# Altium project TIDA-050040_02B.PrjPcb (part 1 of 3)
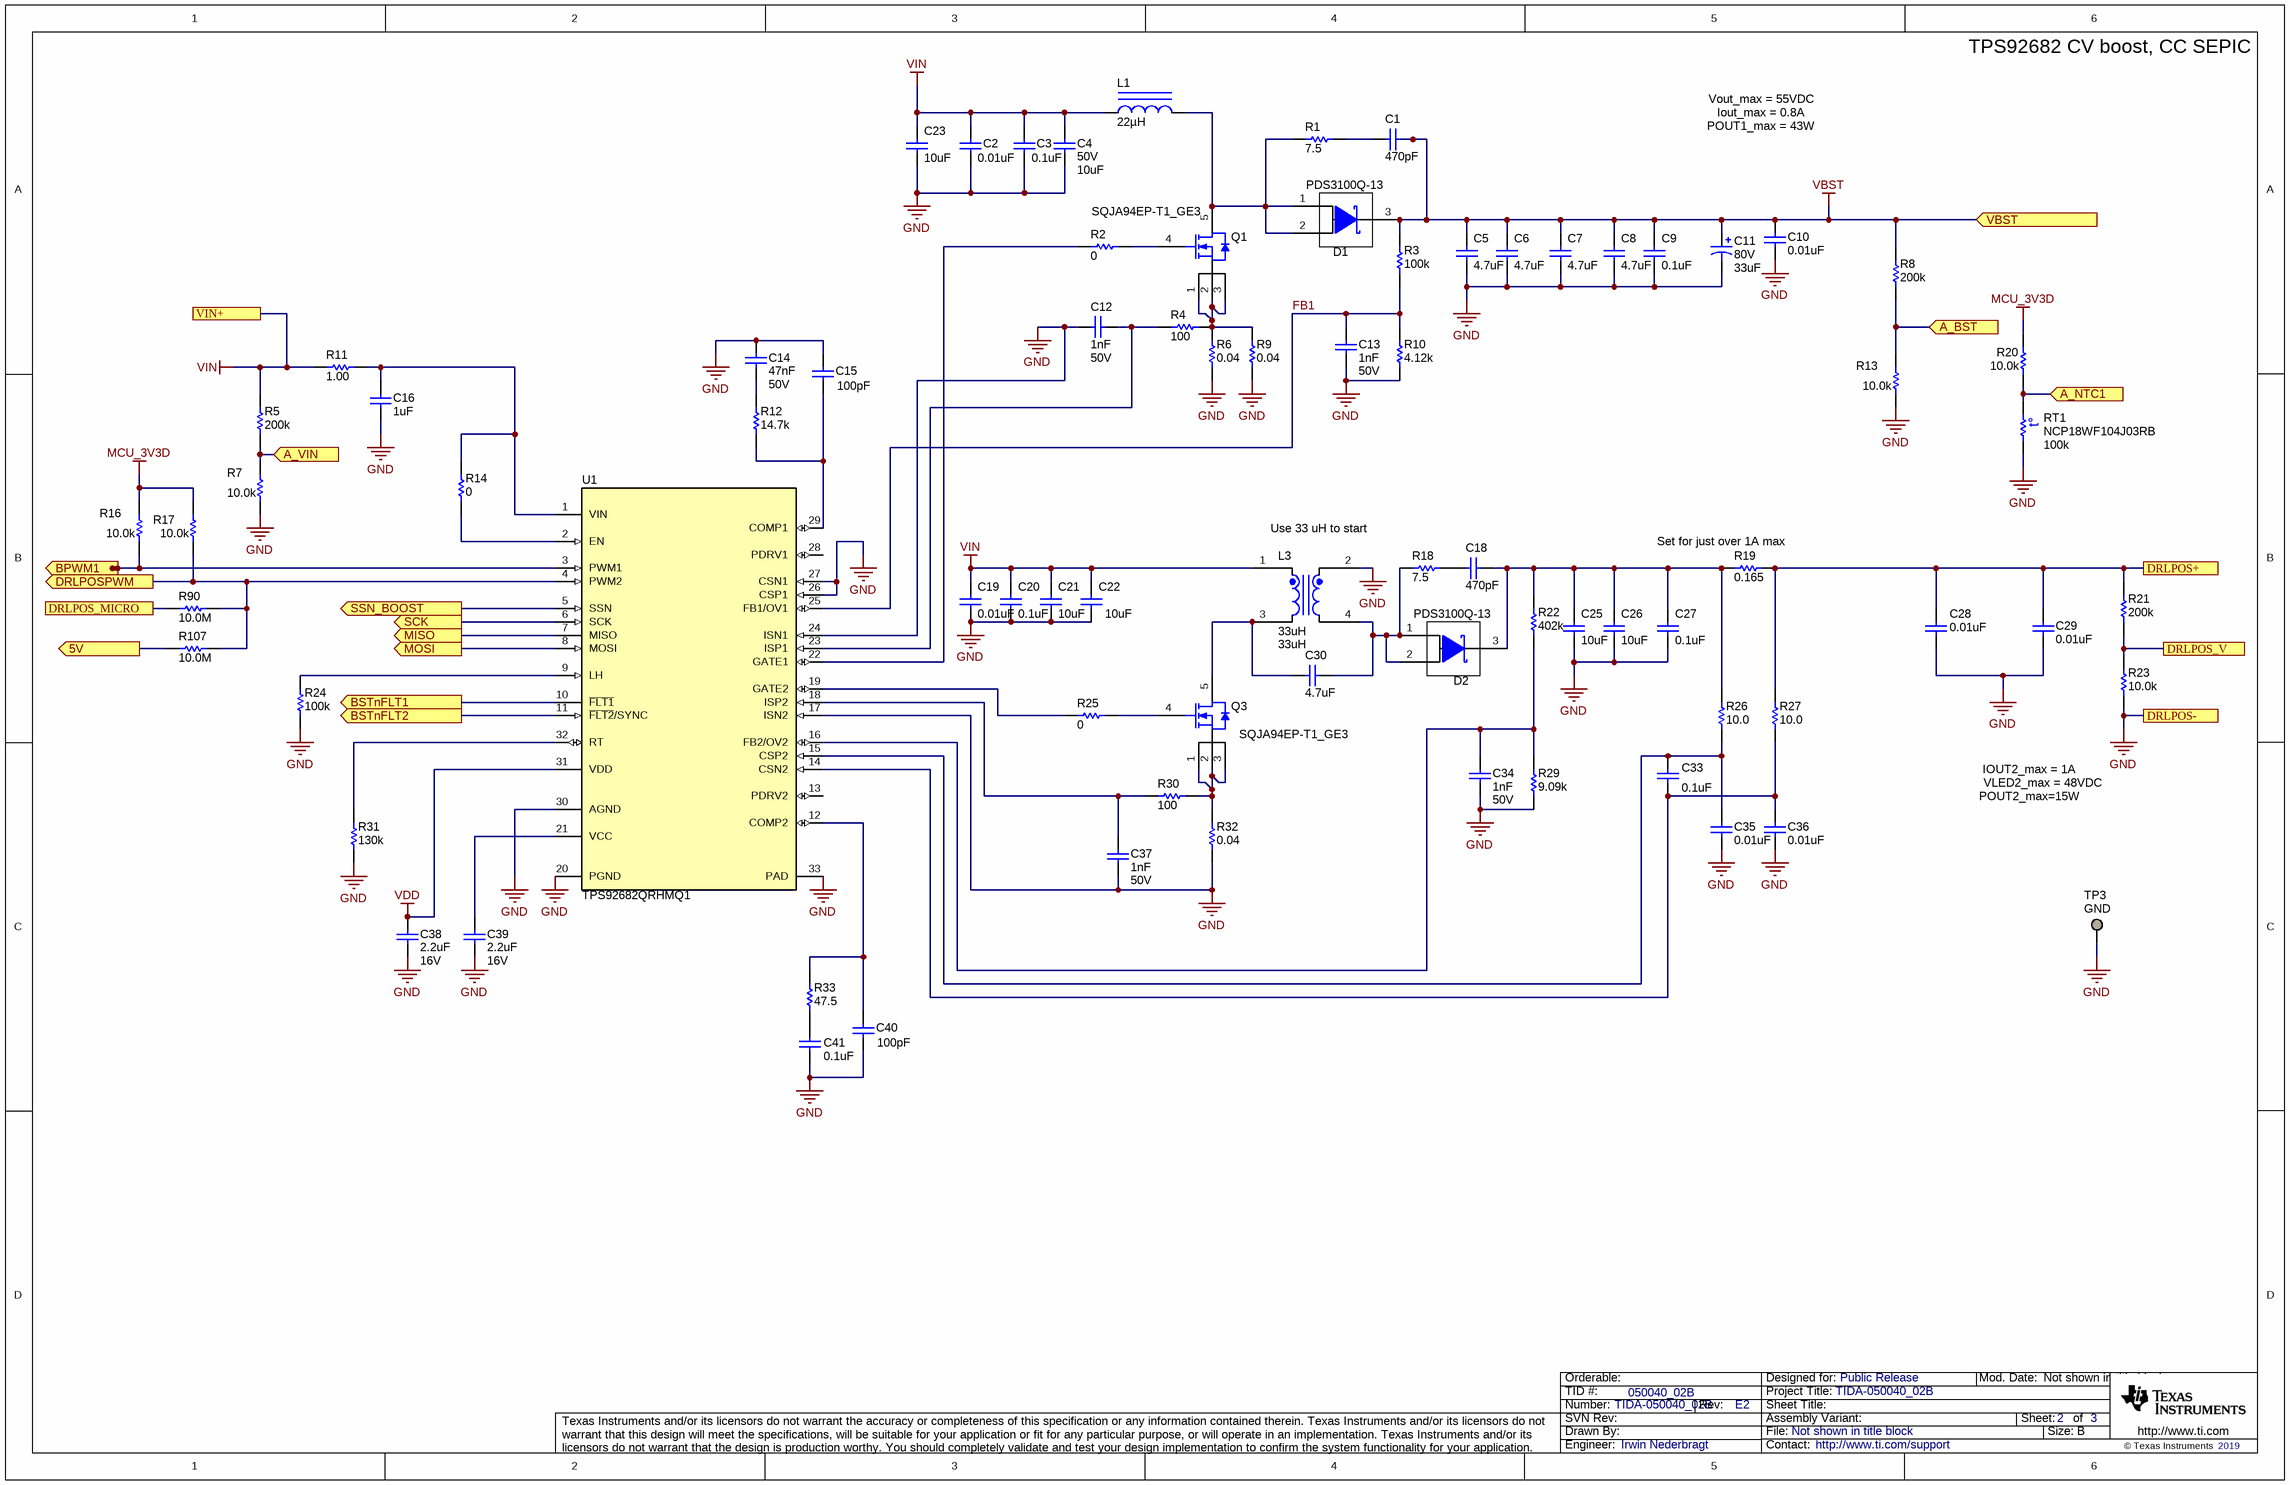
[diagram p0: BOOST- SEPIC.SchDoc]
CopyrightYear: 2019; PCB_Layout: Aaron Hanson; PCB_Rev: E2; PRJ_Customer: Public Release; PRJ_Engineer: Irwin Nederbragt; PRJ_Number: TIDA-050040_02B; PRJ_Title: TIDA-050040_02B; SCH_Rev: E2; TechSupport: http://www.ti.com/support; TID: 050040_02B
6 sheets, 346 parts. Net scope: flat (ports and power ports of the same name join across sheets).
Board file: TIDA-050040.PcbDoc
Sheets:
  BOOST- SEPIC.SchDoc
  Buck.SchDoc
  EVM_Hardware.SchDoc
  TIDA-050040_Battery.SchDoc
  TIDA-050040_MSP432E4x.SchDoc
  TIDA-050040_PwrSupplies.SchDoc

## Sheet BOOST- SEPIC.SchDoc
size 431 x 279 mm; Date: Not shown in title block; ApprovedBy: Not shown in title block; CheckedBy: Not shown in title block; Author: Not shown in title block; CompanyName: Not shown in title block; Engineer: Not shown in title block; Organization: Not shown in title block; Address1: Not shown in title block; Address2: Not shown in title block; Address3: Not shown in title block; Address4: Not shown in title block; DocumentNumber: 1; Revision: Use project parameter SCH_Rev; SheetNumber: 2; SheetTotal: 3; PageSetup: Record=PageOptions¦CenterHorizontal=True¦CenterVertical=True¦PrintScale=1.00¦XCorrection=1.00¦YCorrection=1.00¦PrintKind=0¦BorderSize=5000000¦LeftOffset=0¦BottomOffset=0¦Orientation=2¦PaperLength=1000¦PaperWidth=1000¦Scale=100¦PaperSource=15¦PrintQuality=600¦MediaType=1¦DitherType=10¦PaperKind=Letter¦PrintScaleMode=1

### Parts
C1  ValueDisplayed: 470pF  [0603_HV]  (hidden comment: Capacitor)
C2  ValueDisplayed: 0.01uF  [0603_HV]  (hidden comment: Capacitor)
C3  ValueDisplayed: 0.1uF  [0603_HV]  (hidden comment: Capacitor)
C4  VDC_V: 50V  ValueDisplayed: 10uF  [1210_280]  (hidden comment: C3225X7R1H106M250AC)
C5  ValueDisplayed: 4.7uF  [1210_220]  (hidden comment: Capacitor)
C6  ValueDisplayed: 4.7uF  [1210_220]  (hidden comment: Capacitor)
C7  ValueDisplayed: 4.7uF  [1210_220]  (hidden comment: Capacitor)
C8  ValueDisplayed: 4.7uF  [1210_220]  (hidden comment: Capacitor)
C9  ValueDisplayed: 0.1uF  [0603_HV]  (hidden comment: Capacitor)
C10  ValueDisplayed: 0.01uF  [0603_HV]  (hidden comment: Capacitor)
C11  VDC_V: 80V  ValueDisplayed: 33uF  [SM_RADIAL_F]  (hidden comment: EEE-FK1K330P)
C12  Cap_F: 1nF  VDC_V: 50V  [0603]  (hidden comment: C0603C102J5RACAUTO)
C13  Cap_F: 1nF  VDC_V: 50V  [0603]  (hidden comment: C0603C102J5RACAUTO)
C14  Cap_F: 47nF  VDC_V: 50V  [0603]  (hidden comment: 06035C473JAT2A)
C15  ValueDisplayed: 100pF  [0603_HV]  (hidden comment: 885012006057)
C16  ValueDisplayed: 1uF  [1206_180]  (hidden comment: Capacitor)
C18  ValueDisplayed: 470pF  [0603_HV]  (hidden comment: Capacitor)
C19  ValueDisplayed: 0.01uF  [0603_HV]  (hidden comment: Capacitor)
C20  ValueDisplayed: 0.1uF  [0603_HV]  (hidden comment: Capacitor)
C21  ValueDisplayed: 10uF  [1210_280]  (hidden comment: C3225X7R1H106M250AC)
C22  ValueDisplayed: 10uF  [1210_280]  (hidden comment: C3225X7R1H106M250AC)
C23  ValueDisplayed: 10uF  [1210_280]  (hidden comment: C3225X7R1H106M250AC)
C25  ValueDisplayed: 10uF  [1210_280]  (hidden comment: C3225X7R1H106M250AC)
C26  ValueDisplayed: 10uF  [1210_280]  (hidden comment: C3225X7R1H106M250AC)
C27  ValueDisplayed: 0.1uF  [0603_HV]  (hidden comment: Capacitor)
C28  ValueDisplayed: 0.01uF  [0603_HV]  (hidden comment: Capacitor)
C29  ValueDisplayed: 0.01uF  [0603_HV]  (hidden comment: Capacitor)
C30  ValueDisplayed: 4.7uF  [1210_220]  (hidden comment: Capacitor)
C33  ValueDisplayed: 0.1uF  [0603_HV]  (hidden comment: Capacitor)
C34  Cap_F: 1nF  VDC_V: 50V  [0603]  (hidden comment: C0603C102J5RACAUTO)
C35  ValueDisplayed: 0.01uF  [0603_HV]  (hidden comment: Capacitor)
C36  ValueDisplayed: 0.01uF  [0603_HV]  (hidden comment: Capacitor)
C37  Cap_F: 1nF  VDC_V: 50V  [0603]  (hidden comment: C0603C102J5RACAUTO)
C38  ValueDisplayed: 2.2uF  Value2: 16V  [0603_HV]  (hidden comment: Capacitor)
C39  ValueDisplayed: 2.2uF  Value2: 16V  [0603_HV]  (hidden comment: Capacitor)
C40  ValueDisplayed: 100pF  [0603_HV]  (hidden comment: 885012006057)
C41  ValueDisplayed: 0.1uF  [0603_HV]  (hidden comment: CGA3E3X7S2A104K080AB)
D1  PDS3100Q-13  [POWERDI5]
D2  PDS3100Q-13  [POWERDI5]
L1  ValueDisplayed: 22µH  [SPM12565VT]  (hidden comment: SPM12565VT-220M-D)
L3  value 33uH  [MSD1278]  (hidden comment: MSD1278-333ML)
Q1  SQJA94EP-T1_GE3  [PowerPAK_SO-8L]
Q3  SQJA94EP-T1_GE3  [PowerPAK_SO-8L]
R1  ValueDisplayed: 7.5  [2010L]  (hidden comment: Resistor)
R2  ValueDisplayed: 0  [0603_HV]  (hidden comment: CRCW06030000Z0EA)
R3  ValueDisplayed: 100k  [0603_HV]  (hidden comment: CRCW0603100KFKEA)
R4  ValueDisplayed: 100  [0603_HV]  (hidden comment: Resistor)
R5  ValueDisplayed: 200k  [0603]  (hidden comment: CRCW0603200KFKEA)
R6  ValueDisplayed: 0.04  [2010]  (hidden comment: CSRN2010FK40L0)
R7  ValueDisplayed: 10.0k  [0603]  (hidden comment: RMCF0603FT10K0)
R8  ValueDisplayed: 200k  [0603]  (hidden comment: CRCW0603200KFKEA)
R9  ValueDisplayed: 0.04  [2010]  (hidden comment: CSRN2010FK40L0)
R10  ValueDisplayed: 4.12k  [0603_HV]  (hidden comment: CRCW06034K12FKEA)
R11  ValueDisplayed: 1.00  [0805_HV]  (hidden comment: Resistor)
R12  ValueDisplayed: 14.7k  [0603_HV]  (hidden comment: ERJ-3EKF1472V)
R13  ValueDisplayed: 10.0k  [0603]  (hidden comment: RMCF0603FT10K0)
R14  ValueDisplayed: 0  [0603]  (hidden comment: CRCW06030000Z0EA)
R16  ValueDisplayed: 10.0k  [0603]  (hidden comment: RMCF0603FT10K0)
R17  ValueDisplayed: 10.0k  [0603]  (hidden comment: RMCF0603FT10K0)
R18  ValueDisplayed: 7.5  [2010L]  (hidden comment: Resistor)
R19  ValueDisplayed: 0.165  [1206]  (hidden comment: PT1206FR-070R165L)
R20  ValueDisplayed: 10.0k  [0603]  (hidden comment: RMCF0603FT10K0)
R21  ValueDisplayed: 200k  [0603]  (hidden comment: CRCW0603200KFKEA)
R22  ValueDisplayed: 402k  [0603_HV]  (hidden comment: CRCW0603402KFKEA)
R23  ValueDisplayed: 10.0k  [0603]  (hidden comment: CRCW060310K0FKEA)
R24  ValueDisplayed: 100k  [0603_HV]  (hidden comment: Resistor)
R25  ValueDisplayed: 0  [0603_HV]  (hidden comment: CRCW06030000Z0EA)
R26  ValueDisplayed: 10.0  [0603_HV]  (hidden comment: Resistor)
R27  ValueDisplayed: 10.0  [0603_HV]  (hidden comment: Resistor)
R29  ValueDisplayed: 9.09k  [0603_HV]  (hidden comment: CRCW06039K09FKEA)
R30  ValueDisplayed: 100  [0603_HV]  (hidden comment: Resistor)
R31  ValueDisplayed: 130k  [0603_HV]  (hidden comment: CRCW0603130KFKEA)
R32  ValueDisplayed: 0.04  [2010]  (hidden comment: CSRN2010FK40L0)
R33  ValueDisplayed: 47.5  [0603_HV]  (hidden comment: CRCW060347R5FKEA)
R90  ValueDisplayed: 10.0M  [0603]  (hidden comment: CRCW060310M0FKEA)
R107  ValueDisplayed: 10.0M  [0603]  (hidden comment: CRCW060310M0FKEA)
RT1  NCP18WF104J03RB  value 100k  [0603S]
TP3  GND  [Keystone1502-2]
U1  TPS92682QRHMQ1  [RHM0032C]

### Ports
5V, A_BST, A_NTC1, A_VIN, BPWM1, BSTnFLT1, BSTnFLT2, DRLPOS+, DRLPOS-, DRLPOS_MICRO, DRLPOS_V, DRLPOSPWM, MISO, MOSI, SCK, SSN_BOOST, VBST, VIN+

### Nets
5V: R107.1 ; port 5V
GND: C2.1 C3.1 C4.2 C5.2 C6.2 C7.2 C8.2 C9.2 C10.1 C11.2(-) C12.1 C13.1 C14.2 C15.1 C16.2 C19.1 C20.2 C21.2 C22.2 C23.2 C25.2 C26.2 C27.2 C28.2 C29.2 C34.1 C35.2 C36.2 C37.1 C38.1 C39.1 C40.2 C41.2 L3.2 R6.1 R7.1 R9.1 R10.1 R13.1 R23.1 R24.1 R29.1 R31.1 R32.1 RT1.1 TP3.1 U1.17(ISN2) U1.20(PGND) U1.24(ISN1) U1.26(CSP1) U1.27(CSN1) U1.30(AGND) U1.33(PAD) ; port DRLPOS-
MCU_3V3D: R16.2 R17.2 R20.2
VBST: C1.2 C5.1 C6.1 C7.1 C8.1 C9.1 C10.2 C11.1(+) D1.3(K) R3.2 R8.2 ; port VBST
VDD: C38.2 U1.31(VDD)
VIN: C2.2 C3.2 C4.1 C19.2 C20.1 C21.1 C22.1 C23.1 L1.1 L3.1 R5.2 R11.1 ; port VIN+
A_NTC1: R20.1 RT1.2 ; port A_NTC1
BPWM1: R16.1 U1.3(PWM1) ; port BPWM1
DRLPOS+: C28.1 C29.1 R19.2 R21.2 R27.2 ; port DRLPOS+
DRLPOS_MICRO: R90.1 ; port DRLPOS_MICRO
DRLPOSPWM: R17.1 R90.2 R107.2 U1.4(PWM2) ; port DRLPOSPWM
FB1: C13.2 R3.1 R10.2 U1.25(FB1/OV1)
MISOM: U1.7(MISO) ; port MISO
MOSIM: U1.8(MOSI) ; port MOSI
PD3: U1.6(SCK) ; port SCK
PE2: R21.1 R23.2 ; port DRLPOS_V
PE3: R5.1 R7.2 ; port A_VIN
PE4: R8.1 R13.2 ; port A_BST
PM1: U1.11(~{FLT2}/SYNC) ; port BSTnFLT2
PM2: U1.10(~{FLT1}) ; port BSTnFLT1
SSN_BOOST: U1.5(SSN) ; port SSN_BOOST
NetC1_1: C1.1 R1.1
NetC12_2: C12.2 R4.1 U1.23(ISP1)
NetC14_1: C14.1 R12.2
NetC15_2: C15.2 R12.1 U1.29(COMP1)
NetC16_1: C16.1 R11.2 R14.2 U1.1(VIN)
NetC18_1: C18.1 R18.1
NetC18_2: C18.2 C25.1 C26.1 C27.1 D2.3(K) R19.1 R22.2 R26.2
NetC30_1: C30.1 L3.3 Q3.5(D)
NetC30_2: C30.2 D2.1(A) D2.2(A) L3.4 R18.2
NetC33_1: C33.1 C35.1 R26.1 U1.15(CSP2)
NetC33_2: C33.2 C36.1 R27.1 U1.14(CSN2)
NetC34_2: C34.2 R22.1 R29.2 U1.16(FB2/OV2)
NetC37_2: C37.2 R30.1 U1.18(ISP2)
NetC39_2: C39.2 U1.21(VCC)
NetC40_1: C40.1 R33.2 U1.12(COMP2)
NetC41_1: C41.1 R33.1
NetD1_1: D1.1(A) D1.2(A) L1.2 Q1.5(D) R1.2
NetQ1_1: Q1.1(S) Q1.2(S) Q1.3(S) R4.2 R6.2 R9.2
NetQ1_4: Q1.4(G) R2.2
NetQ3_1: Q3.1(S) Q3.2(S) Q3.3(S) R30.2 R32.2
NetQ3_4: Q3.4(G) R25.2
NetR2_1: R2.1 U1.22(GATE1)
NetR14_1: R14.1 U1.2(EN)
NetR24_2: R24.2 U1.9(LH)
NetR25_1: R25.1 U1.19(GATE2)
NetR31_2: R31.2 U1.32(RT)

Not connected (* = marked no-connect by the designer): U1 13(PDRV2) 28(PDRV1)

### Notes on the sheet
- Vout_max = 55VDC
- TPS92682 CV boost, CC SEPIC
- Iout_max = 0.8A
- POUT1_max = 43W
- Use 33 uH to start
- (near R19) Set for just over 1A max
- IOUT2_max = 1A
- POUT2_max=15W
- VLED2_max = 48VDC

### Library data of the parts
C1 C18 = CMP-0007272-4: CAP, CERM, 470 pF, 100 V, +/- 5%, C0G/NP0, 0603; PartNumber: GRM1885C2A471JA01D; Manufacturer: MuRata; Polarized: N; Value: 470pF; U/M: EA; Value1: Unknown; VDC_V: 100V; TaMin_C: -55°C; TaMax_C: 125°C; Cap_Case: 0603; SizeArea_mm2: 1.28; SizeAreaWB_mm2: 4.68; SizeX_mm: 1.6; SizeY_mm: 0.8; SizeZ_mm: 1; AEC Category: Q200
C2 C10 C19 C28 C29 C35 C36 = CMP-0007082-4: CAP, CERM, 0.01 uF, 100 V, +/- 10%, X7R, AEC-Q200 Grade 1, 0603; PartNumber: CGA3E2X7R2A103K080AA; Manufacturer: TDK; Polarized: N; Value: 0.01uF; U/M: EA; Cap_F: 10nF; ESR_ohm: 2.35428d; Value1: 0.235428 ohm; VDC_V: 100V; IRMS_A: 3.96995dA; TaMin_C: -55°C; TaMax_C: 125°C; Cap_Case: 0603; SizeArea_mm2: 1.28; SizeAreaWB_mm2: 4.68; SizeX_mm: 1.6; SizeY_mm: 0.8; SizeZ_mm: 1; AEC Category: Q200; AEC Qualified: Y
C3 C9 C20 C27 C33 = CMP-0007469-4: CAP, CERM, 0.1 uF, 100 V, +/- 10%, X7R, 0603; PartNumber: GRM188R72A104KA35D; Manufacturer: MuRata; Polarized: N; Value: 0.1uF; U/M: EA; Cap_F: 100nF; Value1: Unknown; VDC_V: 100V; TaMin_C: -55°C; TaMax_C: 125°C; Cap_Case: 0603; SizeArea_mm2: 1.28; SizeAreaWB_mm2: 4.68; SizeX_mm: 1.6; SizeY_mm: 0.8; SizeZ_mm: 1; AEC Category: Q200
C4 = CMP-0009120-1: CAP, CERM, 10 uF, 50 V, +/- 20%, X7R, 1210; Manufacturer: TDK; TaMin_C: -55°C; Polarized: N; SizeAreaWB_mm2: 14.7; Value1: Unknown; U/M: EA; Value: 10uF; TaMax_C: 125°C; SizeZ_mm: 2.8; SizeX_mm: 3.2; SizeY_mm: 2.5; Cap_Case: 1210; SizeArea_mm2: 8; CompType: Capacitor; Cap_F: 10µF; AEC Category: Q200
C5-C8 C30 = CMP-0009134-2: CAP, CERM, 4.7 uF, 100 V, +/- 10%, X7S, 1210; PartNumber: C3225X7S2A475K200AB; Manufacturer: TDK; Polarized: N; Value: 4.7uF; U/M: EA; Cap_F: 4.7µF; ESR_ohm: 4.236m; Value1: 0.004236 ohm; VDC_V: 100V; IRMS_A: 3.57337A; TaMin_C: -55°C; TaMax_C: 125°C; SizeArea_mm2: 8; SizeAreaWB_mm2: 14.7; SizeX_mm: 3.2; SizeY_mm: 2.5; SizeZ_mm: 2.2; AEC Category: Q200
C11 = CMP-0011198-2: CAP, AL, 33 uF, 80 V, +/- 20%, 1.3 ohm, AEC-Q200 Grade 2, SMD; Manufacturer: Panasonic; TaMin_C: -55°C; ESR_ohm: 1.3; Polarized: Y; SizeAreaWB_mm2: 123.6; Value1: 1.3 ohm; U/M: EA; Value: 33uF; TaMax_C: 105°C; SizeZ_mm: 10.2; SizeX_mm: 10; SizeY_mm: 8.3; Cap_Case: F; SizeArea_mm2: 83; CompType: Capacitor; Cap_F: 33µF; IRMS_A: 1.3dA; AEC Grade: 2; AEC Category: Q200
C12 C13 C34 C37 = CMP-0006844-4: CAP, CERM, 1000 pF, 50 V, +/- 5%, X7R, AEC-Q200 Grade 1, 0603; Manufacturer: Kemet; TaMin_C: -55°C; Polarized: N; SizeAreaWB_mm2: 4.68; Value1: Unknown; U/M: EA; Value: 1000pF; TaMax_C: 125°C; SizeZ_mm: 1; SizeX_mm: 1.6; SizeY_mm: 0.8; SizeArea_mm2: 1.28; CompType: Capacitor; AEC Qualified: Y; AEC Category: Q200
C14 = CMP-0085252-1: CAP, CERM, 0.047 µF, 50 V,+/- 5%, X7R, 0603; Manufacturer: AVX; TaMax_C: 125°C; Value: 0.047uF; SizeX_mm: 1.6; SizeArea_mm2: 1.28; AEC Category: Q200; SizeY_mm: 0.8; Polarized: N; CompType: Capacitor; SizeAreaWB_mm2: 4.68; U/M: EA; TaMin_C: -55°C; SizeZ_mm: 1
C15 C40 = CMP-0006822-4: CAP, CERM, 100 pF, 50 V, +/- 5%, C0G/NP0, 0603; Manufacturer: Wurth Elektronik; TaMin_C: -55°C; Polarized: N; SizeAreaWB_mm2: 4.68; Value1: Unknown; U/M: EA; Value: 100pF; TaMax_C: 125°C; SizeZ_mm: 1; SizeX_mm: 1.6; SizeY_mm: 0.8; Cap_Case: 0603; Value2: 50V; SizeArea_mm2: 1.28; CompType: Capacitor; AEC Category: Q200
C16 = CMP-0008801-2: CAP, CERM, 1 uF, 100 V, +/- 10%, X7R, 1206; PartNumber: CL31B105KCHNNNE; Manufacturer: Samsung; Polarized: N; Value: 1uF; U/M: EA; Cap_F: 1µF; Value1: Unknown; VDC_V: 100V; TaMin_C: -55°C; TaMax_C: 125°C; Cap_Case: 1206; SizeArea_mm2: 5.12; SizeAreaWB_mm2: 10.92; SizeX_mm: 3.2; SizeY_mm: 1.6; SizeZ_mm: 1.8; AEC Category: Q200
C21-C23 C25 C26 = CMP-0009120-1: CAP, CERM, 10 uF, 50 V, +/- 20%, X7R, 1210; Manufacturer: TDK; TaMin_C: -55°C; Polarized: N; SizeAreaWB_mm2: 14.7; Value1: Unknown; U/M: EA; Value: 10uF; TaMax_C: 125°C; SizeZ_mm: 2.8; SizeX_mm: 3.2; SizeY_mm: 2.5; Cap_Case: 1210; Value2: 50V; SizeArea_mm2: 8; CompType: Capacitor; Cap_F: 10µF; AEC Category: Q200
C38 C39 = CMP-0007499-4: CAP, CERM, 2.2 uF, 16 V, +/- 10%, X7R, 0603; PartNumber: GRM188Z71C225KE43; Manufacturer: MuRata; Polarized: N; Value: 2.2uF; U/M: EA; Cap_F: 2.2µF; Value1: Unknown; TaMin_C: -55°C; TaMax_C: 125°C; Cap_Case: 0603; SizeArea_mm2: 1.28; SizeAreaWB_mm2: 4.68; SizeX_mm: 1.6; SizeY_mm: 0.8; SizeZ_mm: 1; AEC Category: Q200
C41 = CMP-0007099-4: CAP, CERM, 0.1 uF, 100 V, +/- 10%, X7S, AEC-Q200 Grade 1, 0603; Manufacturer: TDK; TaMin_C: -55°C; ESR_ohm: 0.04959; Polarized: N; SizeAreaWB_mm2: 4.68; Value1: 0.04959 ohm; U/M: EA; Value: 0.1uF; TaMax_C: 125°C; SizeZ_mm: 1; SizeX_mm: 1.6; SizeY_mm: 0.8; Cap_Case: 0603; SizeArea_mm2: 1.28; CompType: Capacitor; AEC Qualified: Y; Cap_F: 100nF; VDC_V: 100V; IRMS_A: 7.51618dA; AEC Category: Q200
D1 D2 = CMP-0028754-2: Diode, Schottky, 100 V, 3 A, AEC-Q101, PowerDI5; Manufacturer: Diodes Inc.; Vf_V: 7.6dV; Value: 100V; Value1: 3A; Value2: 0.76V; TJmax_C: 150°C; SizeAreaWB_mm2: 49.56; SizeArea_mm2: 24.96; SizeX_mm: 6.4; SizeY_mm: 3.9; SizeZ_mm: 1.05; AEC Category: Q101; AEC Qualified: Y; Green_Lifecycle: Active; Green_REACh: Passed
L1 = CMP-0084138-1: Inductor, Shielded, 22 µH, 6.9 A, 0.0341 ohm, AEC-Q200 Grade 0, SMD; Manufacturer: TDK; Isat: 14.1A @ 30% inductance drop; Irms: 6.9A @ 40C rise; SizeAreaWB_mm2: 217.5; DCR_ohm: 0.0341; Value: 22uH; Imax_A: 6.9A; SizeZ_mm: 6.5; SizeX_mm: 13; SizeY_mm: 12.5; SizeArea_mm2: 162.5; AEC Qualified: Y; AEC Grade: 0; AEC Category: Q200
L3 = CMP-0012870-2: Coupled inductor, 33 uH, 5.6 A, 0.15 ohm, TH; Manufacturer: Coilcraft; SizeAreaWB_mm2: 204.49; DCR_ohm: 1.5d; SizeZ_mm: 8.05; SizeX_mm: 12.3; SizeArea_mm2: 151.29; Ind_H: 33µH
Q1 Q3 = CMP-0086155-1: MOSFET, N-CH, 80 V, 60 A, AEC-Q101, PowerPAK_SO-8L; Alternate Manufacturer: None; Manufacturer: Vishay-Siliconix; IdsMax_A: 60A; SizeZ_mm: 1.14; SizeArea_mm2: 31.5495; ChMode: Enhancement; AEC Category: Q101; AEC Qualified: Y; Vgs_V: 20V; SizeAreaWB_mm2: 58.1095; Value2: 36 nC; Value1: ? ohm; VdsMax_V: 80V; Value: 80V; QgTyp_nC: 36; SizeY_mm: 5.13; SizeX_mm: 6.15; ChType: N
R1 R18 = CMP-0016180-3: RES, 7.5, 5%, 0.75 W, AEC-Q200 Grade 0, 2010; PartNumber: CRCW20107R50JNEF; Manufacturer: Vishay-Dale; Value: 7.5; Value_Code: 7R50; Power_W: 750mW; Value2: 0.75W; VDC_V: 400V; TempCo: 200 ppm/C; EIA_Code: E24; AEC Category: Q200; AEC Qualified: Y; AEC Grade: 0; SizeArea_mm2: 12.5; SizeX_mm: 5; SizeY_mm: 2.5; SizeZ_mm: 1.66
R2 R25 = CMP-0025697-4: RES, 0, 5%, 0.1 W, AEC-Q200 Grade 0, 0603; Manufacturer: Vishay-Dale; Power_W: 100mW; TempCo: 200 ppm/C; Value_Code: 0000; Value: 0; EIA_Code: E24; SizeX_mm: 1.6; SizeY_mm: 0.8; SizeZ_mm: 1; Value2: 0.1W; SizeArea_mm2: 1.28; CompType: Resistor; AEC Qualified: Y; VDC_V: 75V; AEC Category: Q200
R3 = CMP-0021990-4: RES, 100 k, 1%, 0.1 W, AEC-Q200 Grade 0, 0603; Manufacturer: Vishay-Dale; Power_W: 100mW; TempCo: 100 ppm/C; Value: 100k; EIA_Code: E96; SizeX_mm: 1.6; SizeY_mm: 0.8; SizeZ_mm: 1; Value2: 0.1W; SizeArea_mm2: 1.28; CompType: Resistor; AEC Qualified: Y; VDC_V: 75V; AEC Category: Q200; AEC Grade: 0
R4 R30 = CMP-0021991-4: RES, 100, 1%, 0.1 W, AEC-Q200 Grade 0, 0603; PartNumber: CRCW0603100RFKEA; Manufacturer: Vishay-Dale; Value: 100; Value_Code: 100R; Power_W: 100mW; Value2: 0.1W; VDC_V: 75V; TempCo: 100 ppm/C; SizeArea_mm2: 1.28; SizeX_mm: 1.6; SizeY_mm: 0.8; SizeZ_mm: 1; EIA_Code: E96; AEC Category: Q200; AEC Qualified: Y; AEC Grade: 0
R5 R8 R21 = CMP-0022200-4: RES, 200 k, 1%, 0.1 W, AEC-Q200 Grade 0, 0603; Manufacturer: Vishay-Dale; Power_W: 100mW; TempCo: 100 ppm/C; Value: 200k; EIA_Code: E96; SizeX_mm: 1.6; SizeY_mm: 0.8; SizeZ_mm: 1; Value2: 0.1W; SizeArea_mm2: 1.28; CompType: Resistor; AEC Qualified: Y; VDC_V: 75V; AEC Category: Q200; AEC Grade: 0
R6 R9 R32 = CMP-0016519-2: RES, 0.04, 1%, 1 W, 2010; Manufacturer: Stackpole Electronics Inc; Power_W: 1W; TempCo: 250 ppm/C; Value_Code: R040; U/M: EA; Value: 0.04; SizeX_mm: 5; SizeY_mm: 2.5; SizeZ_mm: 1.66; SizeArea_mm2: 12.5; AEC Category: Q200
R7 R13 R16 R17 R20 = CMP-0023341-3: RES, 10.0 k, 1%, 0.1 W, AEC-Q200 Grade 0, 0603; Manufacturer: Stackpole Electronics Inc; Power_W: 100mW; TempCo: 100 ppm/C; Value_Code: 10k0; U/M: EA; Value: 10.0k; EIA_Code: E96; Res_ohm: 10k; SizeX_mm: 1.6; SizeY_mm: 0.8; SizeZ_mm: 1; Value2: 0.1W; SizeArea_mm2: 1.28; CompType: Resistor; AEC Qualified: Y; VDC_V: 75V; AEC Grade: 0; AEC Category: Q200
R10 = CMP-0022450-4: RES, 4.12 k, 1%, 0.1 W, AEC-Q200 Grade 0, 0603; Manufacturer: Vishay-Dale; Power_W: 100mW; TempCo: 100 ppm/C; Value_Code: 4k12; Value: 4.12k; EIA_Code: E96; SizeX_mm: 1.6; SizeY_mm: 0.8; SizeZ_mm: 1; Value2: 0.1W; SizeArea_mm2: 1.28; CompType: Resistor; AEC Qualified: Y; VDC_V: 75V; AEC Category: Q200; AEC Grade: 0
R11 = CMP-0021009-3: RES, 1.00, 1%, 0.125 W, AEC-Q200 Grade 0, 0805; PartNumber: CRCW08051R00FKEA; Manufacturer: Vishay-Dale; Value: 1.00; Res_ohm: 1; Value_Code: 1R00; Power_W: 125mW; Value2: 0.125W; VDC_V: 150V; TempCo: 100 ppm/C; SizeArea_mm2: 2.5; SizeX_mm: 2; SizeY_mm: 1.25; SizeZ_mm: 1.45; EIA_Code: E96; AEC Category: Q200; AEC Qualified: Y; AEC Grade: 0
R12 = CMP-0022687-3: RES, 14.7 k, 1%, 0.1 W, AEC-Q200 Grade 0, 0603; Manufacturer: Panasonic; Power_W: 100mW; TempCo: 100 ppm/C; Value_Code: 14k7; U/M: EA; Value: 14.7k; EIA_Code: E96; SizeX_mm: 1.6; SizeY_mm: 0.8; SizeZ_mm: 1; Value2: 0.1W; SizeArea_mm2: 1.28; CompType: Resistor; AEC Qualified: Y; VDC_V: 50V; AEC Grade: 0; AEC Category: Q200
R14 = CMP-0025697-4: RES, 0, 5%, 0.1 W, AEC-Q200 Grade 0, 0603; Manufacturer: Vishay-Dale; Power_W: 100mW; TempCo: 200 ppm/C; Value_Code: 0000; Value: 0; EIA_Code: E24; SizeX_mm: 1.6; SizeY_mm: 0.8; SizeZ_mm: 1; Value2: 0.1W; SizeArea_mm2: 1.28; AEC Qualified: Y; VDC_V: 75V; AEC Category: Q200
R19 = CMP-0017835-2: RES, 0.165, 1%, 0.25 W, 1206; Manufacturer: Yageo America; Power_W: 250mW; TempCo: 75 ppm/C; Value_Code: R165; U/M: EA; Value: 0.165; Res_ohm: 1.65d; SizeX_mm: 3.2; SizeY_mm: 1.6; SizeZ_mm: 1.35; Value2: 0.25W; SizeArea_mm2: 5.12; AEC Qualified: N; AEC Category: Q200
R22 = CMP-0022408-4: RES, 402 k, 1%, 0.1 W, AEC-Q200 Grade 0, 0603; Manufacturer: Vishay-Dale; Power_W: 100mW; TempCo: 100 ppm/C; Value: 402k; EIA_Code: E96; SizeX_mm: 1.6; SizeY_mm: 0.8; SizeZ_mm: 1; Value2: 0.1W; SizeArea_mm2: 1.28; CompType: Resistor; AEC Qualified: Y; VDC_V: 75V; AEC Category: Q200; AEC Grade: 0
R23 = CMP-0021998-4: RES, 10.0 k, 1%, 0.1 W, AEC-Q200 Grade 0, 0603; Manufacturer: Vishay-Dale; Power_W: 100mW; TempCo: 100 ppm/C; Value_Code: 10k0; Value: 10.0k; EIA_Code: E96; Res_ohm: 10k; SizeX_mm: 1.6; SizeY_mm: 0.8; SizeZ_mm: 1; Value2: 0.1W; SizeArea_mm2: 1.28; CompType: Resistor; AEC Qualified: Y; VDC_V: 75V; AEC Category: Q200; AEC Grade: 0
R24 = CMP-0021990-4: RES, 100 k, 1%, 0.1 W, AEC-Q200 Grade 0, 0603; PartNumber: CRCW0603100KFKEA; Manufacturer: Vishay-Dale; Value: 100k; Power_W: 100mW; Value2: 0.1W; VDC_V: 75V; TempCo: 100 ppm/C; SizeArea_mm2: 1.28; SizeX_mm: 1.6; SizeY_mm: 0.8; SizeZ_mm: 1; EIA_Code: E96; AEC Category: Q200; AEC Qualified: Y; AEC Grade: 0
R26 R27 = CMP-0022003-4: RES, 10.0, 1%, 0.1 W, AEC-Q200 Grade 0, 0603; PartNumber: CRCW060310R0FKEA; Manufacturer: Vishay-Dale; Value: 10.0; Res_ohm: 10; Value_Code: 10R0; Power_W: 100mW; Value2: 0.1W; VDC_V: 75V; TempCo: 100 ppm/C; SizeArea_mm2: 1.28; SizeX_mm: 1.6; SizeY_mm: 0.8; SizeZ_mm: 1; EIA_Code: E96; AEC Category: Q200; AEC Qualified: Y; AEC Grade: 0
R29 = CMP-0022665-4: RES, 9.09 k, 1%, 0.1 W, AEC-Q200 Grade 0, 0603; Manufacturer: Vishay-Dale; Power_W: 100mW; TempCo: 100 ppm/C; Value_Code: 9k09; Value: 9.09k; EIA_Code: E96; SizeX_mm: 1.6; SizeY_mm: 0.8; SizeZ_mm: 1; Value2: 0.1W; SizeArea_mm2: 1.28; CompType: Resistor; AEC Qualified: Y; VDC_V: 75V; AEC Category: Q200; AEC Grade: 0
R31 = CMP-0022036-4: RES, 130 k, 1%, 0.1 W, AEC-Q200 Grade 0, 0603; Manufacturer: Vishay-Dale; Power_W: 100mW; TempCo: 100 ppm/C; Value: 130k; EIA_Code: E96; SizeX_mm: 1.6; SizeY_mm: 0.8; SizeZ_mm: 1; Value2: 0.1W; SizeArea_mm2: 1.28; CompType: Resistor; AEC Qualified: Y; VDC_V: 75V; AEC Category: Q200; AEC Grade: 0
R33 = CMP-0022440-4: RES, 47.5, 1%, 0.1 W, AEC-Q200 Grade 0, 0603; Manufacturer: Vishay-Dale; Power_W: 100mW; TempCo: 100 ppm/C; Value_Code: 47R5; Value: 47.5; EIA_Code: E96; SizeX_mm: 1.6; SizeY_mm: 0.8; SizeZ_mm: 1; Value2: 0.1W; SizeArea_mm2: 1.28; CompType: Resistor; AEC Qualified: Y; VDC_V: 75V; AEC Category: Q200; AEC Grade: 0
R90 R107 = CMP-0022002-4: RES, 10.0 M, 1%, 0.1 W, AEC-Q200 Grade 0, 0603; Manufacturer: Vishay-Dale; Power_W: 100mW; TempCo: 100 ppm/C; Value_Code: 10M0; Value: 10.0Meg; EIA_Code: E96; Res_ohm: 10M; SizeX_mm: 1.6; SizeY_mm: 0.8; SizeZ_mm: 1; Value2: 0.1W; SizeArea_mm2: 1.28; AEC Qualified: Y; VDC_V: 75V; AEC Category: Q200; AEC Grade: 0
RT1 = CMP-0002534-3: Thermistor NTC, 100k ohm, 5%, 0603; Manufacturer: MuRata; TaMax_C: 125°C; SizeX_mm: 1.6; SizeY_mm: 0.8; TaMin_C: -40°C; Power_W: 100mW; SizeZ_mm: 1; SizeArea_mm2: 1.28; SizeAreaWB_mm2: 4.68; U/M: EA
TP3 = CMP-0055113-1: Terminal, Turret, TH, Double; PartNumber: 1502-2; Manufacturer: Keystone; CompType: Turret Terminal; Green_Lifecycle: Active; Green_REACh: Passed; CNHeader: FALSE
U1 = CMP-0084188-3: Dual Channel Constant Voltage and Constant Current Controller with SPI Interface, RHM0032C (VQFNP-32); Alternate Manufacturer: Texas Instruments; SizeAreaWB_mm2: 49; Rating: Automotive; SizeZ_mm: 0.9; SizeX_mm: 5; SizeArea_mm2: 25; CompType: IC; AEC Qualified: Y; AEC Category: Q200

## Sheet Buck.SchDoc
size 431 x 279 mm; Date: Not shown in title block; ApprovedBy: Not shown in title block; CheckedBy: Not shown in title block; Author: Not shown in title block; CompanyName: Not shown in title block; Engineer: Not shown in title block; Organization: Not shown in title block; Address1: Not shown in title block; Address2: Not shown in title block; Address3: Not shown in title block; Address4: Not shown in title block; DocumentNumber: 1; Revision: Use project parameter SCH_Rev; SheetNumber: 2; SheetTotal: 3; PageSetup: Record=PageOptions¦CenterHorizontal=True¦CenterVertical=True¦PrintScale=1.00¦XCorrection=1.00¦YCorrection=1.00¦PrintKind=0¦BorderSize=5000000¦LeftOffset=0¦BottomOffset=0¦Orientation=2¦PaperLength=1000¦PaperWidth=1000¦Scale=100¦PaperSource=15¦PrintQuality=600¦MediaType=1¦DitherType=10¦PaperKind=Letter¦PrintScaleMode=1
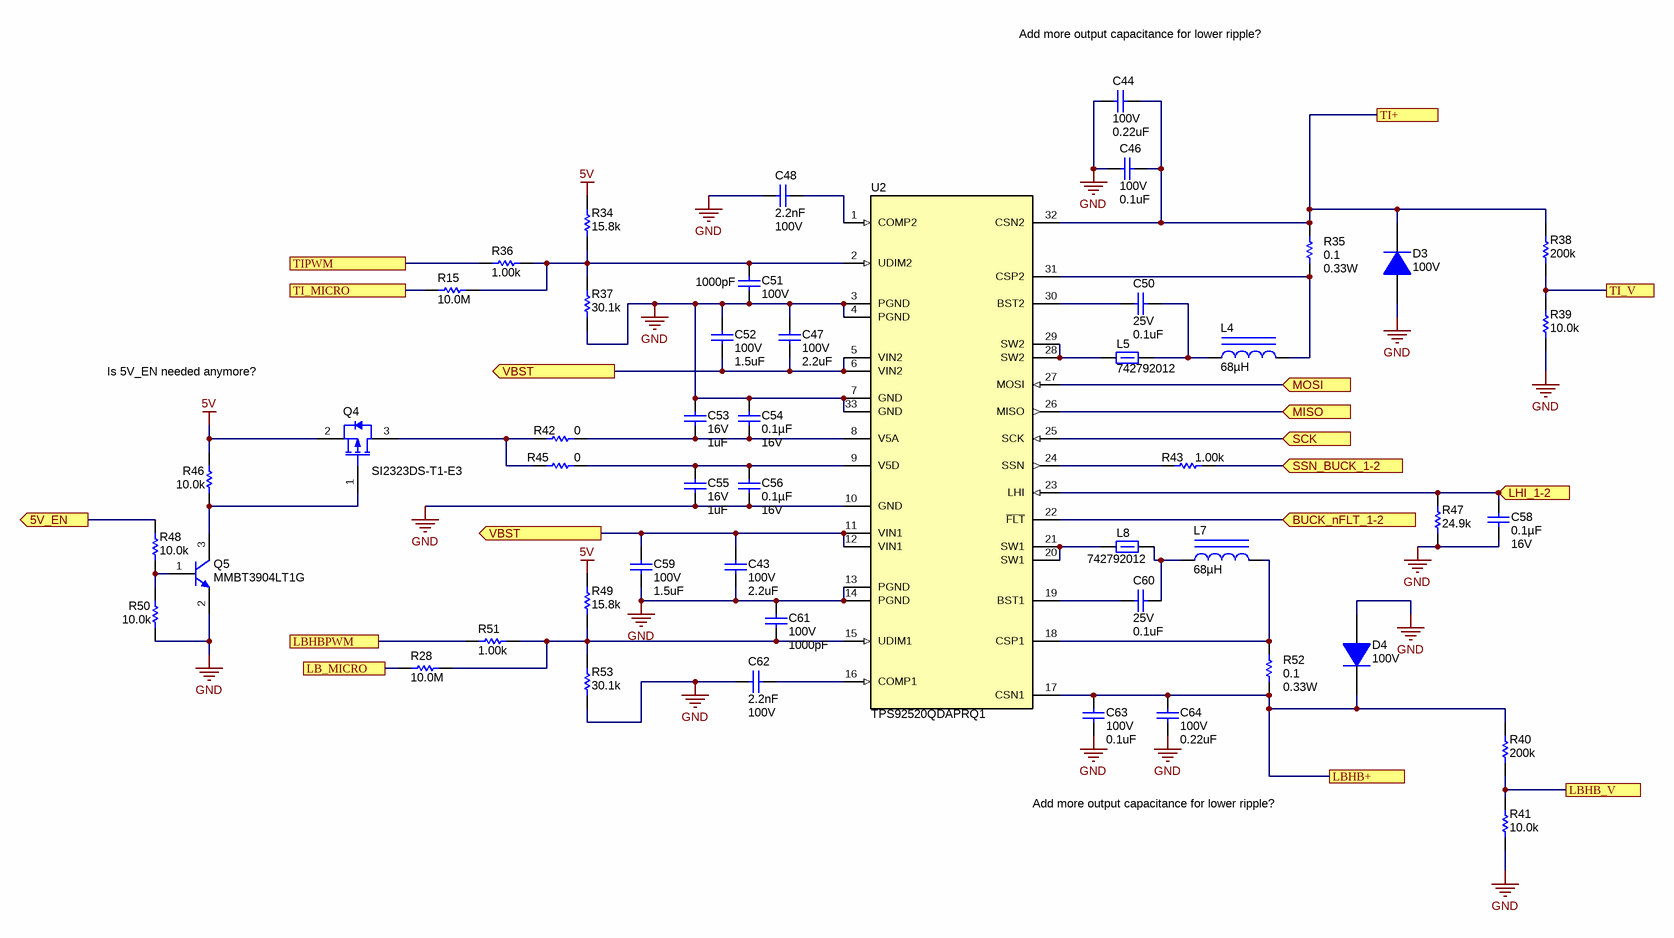
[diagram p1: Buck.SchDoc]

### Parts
C43  VDC_V: 100V  ValueDisplayed: 2.2uF  [1206_190]  (hidden comment: CGA5L3X7S2A225M160AB)
C44  VDC_V: 100V  ValueDisplayed: 0.22uF  [0805_HV]  (hidden comment: CGA4F3X7S2A224M085AE)
C46  VDC_V: 100V  ValueDisplayed: 0.1uF  [0603]  (hidden comment: CGA3E3X7S2A104K080AB)
C47  VDC_V: 100V  ValueDisplayed: 2.2uF  [1206_190]  (hidden comment: CGA5L3X7S2A225M160AB)
C48  Cap_F: 2.2nF  VDC_V: 100V  [0603]  (hidden comment: CGA3E2X7R2A222K080AA)
C50  VDC_V: 25V  ValueDisplayed: 0.1uF  [0603]  (hidden comment: CGA3E2X7R1E104K080AA)
C51  VDC_V: 100V  ValueDisplayed: 1000pF  [0603]  (hidden comment: GRM188R72A102KA01D)
C52  VDC_V: 100V  ValueDisplayed: 1.5uF  [1210_220]  (hidden comment: CGA6M3X7R2A155K200AB)
C53  VDC_V: 16V  ValueDisplayed: 1uF  [0603]  (hidden comment: GCM188R71C105KA64D)
C54  ValueDisplayed: 0.1µF  VDC_V: 16V  [0603]  (hidden comment: CL10B104KO8WPNC)
C55  VDC_V: 16V  ValueDisplayed: 1uF  [0603]  (hidden comment: GCM188R71C105KA64D)
C56  ValueDisplayed: 0.1µF  VDC_V: 16V  [0603]  (hidden comment: CL10B104KO8WPNC)
C58  ValueDisplayed: 0.1µF  VDC_V: 16V  [0603]  (hidden comment: CL10B104KO8WPNC)
C59  VDC_V: 100V  ValueDisplayed: 1.5uF  [1210_220]  (hidden comment: CGA6M3X7R2A155K200AB)
C60  VDC_V: 25V  ValueDisplayed: 0.1uF  [0603]  (hidden comment: CGA3E2X7R1E104K080AA)
C61  VDC_V: 100V  ValueDisplayed: 1000pF  [0603]  (hidden comment: GRM188R72A102KA01D)
C62  Cap_F: 2.2nF  VDC_V: 100V  [0603]  (hidden comment: CGA3E2X7R2A222K080AA)
C63  VDC_V: 100V  ValueDisplayed: 0.1uF  [0603]  (hidden comment: CGA3E3X7S2A104K080AB)
C64  VDC_V: 100V  ValueDisplayed: 0.22uF  [0805_HV]  (hidden comment: CGA4F3X7S2A224M085AE)
D3  value 100V  [SOD-123]  (hidden comment: BAS16D-E3-08)
D4  value 100V  [SOD-123]  (hidden comment: BAS16D-E3-08)
L4  ValueDisplayed: 68µH  [SPM6545VT]  (hidden comment: SPM6545VT-680M-D)
L5  742792012  [0805_HV]
L7  ValueDisplayed: 68µH  [SPM6545VT]  (hidden comment: SPM6545VT-680M-D)
L8  742792012  [0805_HV]
Q4  SI2323DS-T1-E3  [SOT-23]
Q5  MMBT3904LT1G  [SOT-23]
R15  ValueDisplayed: 10.0M  [0603]  (hidden comment: CRCW060310M0FKEA)
R28  ValueDisplayed: 10.0M  [0603]  (hidden comment: CRCW060310M0FKEA)
R34  ValueDisplayed: 15.8k  [0603]  (hidden comment: CRCW060315K8FKEA)
R35  Value2: 0.33W  ValueDisplayed: 0.1  [1210]  (hidden comment: ERJ-L14KF10CU)
R36  ValueDisplayed: 1.00k  [0603]  (hidden comment: CRCW06031K00FKEA)
R37  ValueDisplayed: 30.1k  [0603]  (hidden comment: CRCW060330K1FKEA)
R38  ValueDisplayed: 200k  [0603]  (hidden comment: CRCW0603200KFKEA)
R39  ValueDisplayed: 10.0k  [0603]  (hidden comment: CRCW060310K0FKEA)
R40  ValueDisplayed: 200k  [0603]  (hidden comment: CRCW0603200KFKEA)
R41  ValueDisplayed: 10.0k  [0603]  (hidden comment: CRCW060310K0FKEA)
R42  ValueDisplayed: 0  [0603]  (hidden comment: ERJ-3GEY0R00V)
R43  ValueDisplayed: 1.00k  [0603]  (hidden comment: CRCW06031K00FKEA)
R45  ValueDisplayed: 0  [0603]  (hidden comment: ERJ-3GEY0R00V)
R46  ValueDisplayed: 10.0k  [0603]  (hidden comment: RMCF0603FT10K0)
R47  ValueDisplayed: 24.9k  [0603]  (hidden comment: CRCW060324K9FKEA)
R48  ValueDisplayed: 10.0k  [0603]  (hidden comment: RMCF0603FT10K0)
R49  ValueDisplayed: 15.8k  [0603]  (hidden comment: CRCW060315K8FKEA)
R50  ValueDisplayed: 10.0k  [0603]  (hidden comment: RMCF0603FT10K0)
R51  ValueDisplayed: 1.00k  [0603]  (hidden comment: CRCW06031K00FKEA)
R52  Value2: 0.33W  ValueDisplayed: 0.1  [1210]  (hidden comment: ERJ-L14KF10CU)
R53  ValueDisplayed: 30.1k  [0603]  (hidden comment: CRCW060330K1FKEA)
U2  TPS92520QDAPRQ1  [DAP0032A_N]

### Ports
5V_EN, BUCK_nFLT_1-2, LB_MICRO, LBHB+, LBHB_V, LBHBPWM, LHI_1-2, MISO, MOSI, SCK, SSN_BUCK_1-2, TI+, TI_MICRO, TI_V, TIPWM, VBST

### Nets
5V: Q4.2(S) R34.2 R46.2 R49.2
GND: C43.1 C44.2 C46.2 C47.2 C48.2 C51.2 C52.1 C53.1 C54.1 C55.2 C56.2 C58.2 C59.2 C61.1 C62.2 C63.1 C64.2 D3.2(A) D4.2(A) Q5.2(E) R37.1 R39.1 R41.1 R47.1 R50.1 R53.1 U2.3(PGND) U2.4(PGND) U2.7(GND) U2.10(GND) U2.13(PGND) U2.14(PGND) U2.33(GND)
VBST: C43.2 C47.1 C52.2 C59.1 U2.5(VIN2) U2.6(VIN2) U2.11(VIN1) U2.12(VIN1) ; port VBST
BUCK_nFLT_1-2: U2.22(~{FLT}) ; port BUCK_nFLT_1-2
LB_MICRO: R28.1 ; port LB_MICRO
LBHB+: C63.2 C64.1 D4.1(K) R40.2 R52.1 U2.17(CSN1) ; port LBHB+
LBHBPWM: R51.1 ; port LBHBPWM
LHI_1-2: C58.1 R47.2 U2.23(LHI) ; port LHI_1-2
MISOM: U2.26(MISO) ; port MISO
MOSIM: U2.27(MOSI) ; port MOSI
PD3: U2.25(SCK) ; port SCK
PE0: R40.1 R41.2 ; port LBHB_V
PE1: R38.1 R39.2 ; port TI_V
PL4: R48.2 ; port 5V_EN
SSN_BUCK_1-2: R43.2 ; port SSN_BUCK_1-2
TI+: C44.1 C46.1 D3.1(K) R35.2 R38.2 U2.32(CSN2) ; port TI+
TI_MICRO: R15.1 ; port TI_MICRO
TIPWM: R36.1 ; port TIPWM
NetC48_1: C48.1 U2.1(COMP2)
NetC50_1: C50.1 L4.1 L5.2
NetC50_2: C50.2 U2.30(BST2)
NetC51_1: C51.1 R15.2 R34.1 R36.2 R37.2 U2.2(UDIM2)
NetC53_2: C53.2 C54.2 R42.2 U2.8(V5A)
NetC55_1: C55.1 C56.1 R45.2 U2.9(V5D)
NetC60_1: C60.1 L7.1 L8.2
NetC60_2: C60.2 U2.19(BST1)
NetC61_2: C61.2 R28.2 R49.1 R51.2 R53.2 U2.15(UDIM1)
NetC62_1: C62.1 U2.16(COMP1)
NetL4_2: L4.2 R35.1 U2.31(CSP2)
NetL5_1: L5.1 U2.28(SW2) U2.29(SW2)
NetL7_2: L7.2 R52.2 U2.18(CSP1)
NetL8_1: L8.1 U2.20(SW1) U2.21(SW1)
NetQ4_1: Q4.1(G) Q5.3(C) R46.1
NetQ4_3: Q4.3(D) R42.1 R45.1
NetQ5_1: Q5.1(B) R48.1 R50.2
NetR43_1: R43.1 U2.24(SSN)

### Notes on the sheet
- Add more output capacitance for lower ripple?
- Is 5V_EN needed anymore?

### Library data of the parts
C43 C47 = CMP-0008791-2: CAP, CERM, 2.2 uF, 100 V, +/- 20%, X7S, AEC-Q200 Grade 1, 1206_190; Manufacturer: TDK; Alternate Manufacturer: Taiyo Yuden; Alternate PartNumber: HMJ316BC7225MLHTE; TaMin_C: -55°C; Polarized: N; SizeAreaWB_mm2: 10.92; Value1: Unknown; U/M: EA; Value: 2.2uF; TaMax_C: 125°C; SizeZ_mm: 1.9; SizeX_mm: 3.2; SizeY_mm: 1.6; Cap_Case: 1206; SizeArea_mm2: 5.12; CompType: Capacitor; AEC Qualified: Y; Cap_F: 2.2µF; AEC Grade: 1; AEC Category: Q200
C44 C64 = CMP-0007981-2: CAP, CERM, 0.22 uF, 100 V, +/- 10%, X7S, AEC-Q200 Grade 1, 0805; Manufacturer: TDK; Alternate Manufacturer: Taiyo Yuden; Alternate PartNumber: HMJ212BB7224KGHT; TaMin_C: -55°C; Polarized: N; SizeAreaWB_mm2: 6.75; U/M: EA; Value: 0.22uF; TaMax_C: 125°C; SizeZ_mm: 1.45; SizeX_mm: 2; SizeY_mm: 1.25; Cap_Case: 0805; SizeArea_mm2: 2.5; CompType: Capacitor; AEC Qualified: Y; Cap_F: 220nF; AEC Grade: 1; AEC Category: Q200; ESR_ohm: 0.019477; IRMS_A: 1.48561A; Value1: 0.019477 ohm
C46 C63 = CMP-0007099-4: CAP, CERM, 0.1 uF, 100 V, +/- 10%, X7S, AEC-Q200 Grade 1, 0603; Manufacturer: TDK; TaMin_C: -55°C; ESR_ohm: 0.04959; Polarized: N; SizeAreaWB_mm2: 4.68; Value1: 0.04959 ohm; U/M: EA; Value: 0.1uF; TaMax_C: 125°C; SizeZ_mm: 1; SizeX_mm: 1.6; SizeY_mm: 0.8; SizeArea_mm2: 1.28; CompType: Capacitor; AEC Qualified: Y; Cap_F: 100nF; IRMS_A: 7.51618dA; AEC Category: Q200
C48 C62 = CMP-0007085-4: CAP, CERM, 2200 pF, 100 V, +/- 10%, X7R, AEC-Q200 Grade 1, 0603; Manufacturer: TDK; TaMin_C: -55°C; ESR_ohm: 9.23948d; Polarized: N; SizeAreaWB_mm2: 4.68; Value1: 0.923948 ohm; U/M: EA; Value: 2200pF; TaMax_C: 125°C; SizeZ_mm: 1; SizeX_mm: 1.6; SizeY_mm: 0.8; SizeArea_mm2: 1.28; CompType: Capacitor; AEC Qualified: Y; IRMS_A: 2.95638dA; AEC Category: Q200
C50 C60 = CMP-0007077-5: CAP, CERM, 0.1 uF, 25 V, +/- 10%, X7R, AEC-Q200 Grade 1, 0603; Manufacturer: TDK; TaMin_C: -55°C; Polarized: N; SizeAreaWB_mm2: 4.68; Value1: Unknown; U/M: EA; Value: 0.1uF; TaMax_C: 125°C; SizeZ_mm: 1; SizeX_mm: 1.6; SizeY_mm: 0.8; SizeArea_mm2: 1.28; CompType: Capacitor; AEC Qualified: Y; Cap_F: 100nF; AEC Category: Q200
C51 C61 = CMP-0007467-4: CAP, CERM, 1000 pF, 100 V, +/- 10%, X7R, 0603; Manufacturer: MuRata; TaMin_C: -55°C; Polarized: N; SizeAreaWB_mm2: 4.68; Value1: Unknown; U/M: EA; Value: 1000pF; TaMax_C: 125°C; SizeZ_mm: 1; SizeX_mm: 1.6; SizeY_mm: 0.8; SizeArea_mm2: 1.28; CompType: Capacitor; Cap_F: 1nF; AEC Category: Q200
C52 C59 = CMP-0009148-2: CAP, CERM, 1.5 uF, 100 V, +/- 10%, X7R, AEC-Q200 Grade 1, 1210; Manufacturer: TDK; TaMin_C: -55°C; ESR_ohm: 3.867m; Polarized: N; SizeAreaWB_mm2: 14.7; Value1: 0.003867 ohm; U/M: EA; Value: 1.5uF; TaMax_C: 125°C; SizeZ_mm: 2.2; SizeX_mm: 3.2; SizeY_mm: 2.5; SizeArea_mm2: 8; CompType: Capacitor; AEC Qualified: Y; Cap_F: 1.5µF; IRMS_A: 3.74252A; AEC Grade: 1; AEC Category: Q200
C53 C55 = CMP-0007136-5: CAP, CERM, 1 uF, 16 V, +/- 10%, X7R, AEC-Q200 Grade 1, 0603; Manufacturer: MuRata; TaMin_C: -55°C; Polarized: N; SizeAreaWB_mm2: 4.68; Value1: Unknown; U/M: EA; Value: 1uF; TaMax_C: 125°C; SizeZ_mm: 1; SizeX_mm: 1.6; SizeY_mm: 0.8; SizeArea_mm2: 1.28; CompType: Capacitor; AEC Qualified: Y; Cap_F: 1µF; AEC Category: Q200
C54 C56 C58 = CMP-0085536-1: CAP, CERM, 0.1 µF, 16 V,+/- 10%, X7R, 0603; Manufacturer: Samsung Electro-Mechanics; SizeArea_mm2: 1.28; SizeY_mm: 0.8; AEC Category: Q200; Polarized: N; AEC Qualified: Y; Cap_F: 100nF; TaMax_C: 125°C; SizeZ_mm: 1; U/M: EA; SizeX_mm: 1.6; Value: 0.1uF; TaMin_C: -55°C; CompType: Capacitor; SizeAreaWB_mm2: 4.68
D3 D4 = CMP-0080761-2: Diode, Switching, 100 V, 0.25 A, AEC-Q101, SOD-123; Manufacturer: Vishay-Semiconductor; Io_A: 2.5dA; SizeAreaWB_mm2: 13.095; Value1: 0.25A; TJmax_C: 150°C; SizeZ_mm: 1.35; SizeX_mm: 3.85; SizeY_mm: 1.7; Vf_V: 1.25V; SizeArea_mm2: 6.545; AEC Qualified: Y; AEC Category: Q101
L4 L7 = CMP-0081480-2: Inductor, Shielded, Metal Composite, 68 µH, 1.8 A, 0.316 ohm, SMD; Manufacturer: TDK; Isat: 3.9A @ 30% inductance drop; Irms: 1.8A @ 40C rise; SizeAreaWB_mm2: 76.5; DCR_ohm: 3.16d; Value: 68uH; Imax_A: 1.8A; SizeZ_mm: 4.5; SizeX_mm: 7; SizeY_mm: 6.5; SizeArea_mm2: 45.5; AEC Qualified: N; AEC Category: Q200
L5 L8 = CMP-0003069-1: Ferrite Bead, 33 ohm @ 100 MHz, 4 A, 0805; Manufacturer: Wurth Elektronik; Ztyp@1GHz_Ohm: 65.242; ZTyp@100MHz_Ohm: 33; SizeAreaWB_mm2: 6.75; DCR_ohm: 8m; Value1: 0.008 ohm; Value: 33 ohm; Imax_A: 4A; SizeZ_mm: 1.45; SizeX_mm: 2; SizeY_mm: 1.25; SizeArea_mm2: 2.5
Q4 = CMP-0077896-2: MOSFET, P-CH, -20 V, -3.7 A, SOT-23; Alternate Manufacturer: None; Manufacturer: Vishay-Siliconix; Vgs_V: -8V; Green_REACh: Incomplete; Value2: 12.5 nC; SizeX_mm: 2.5; AEC Category: Q101; IdsMax_A: -3.7A; Green_Lifecycle: Not Set; ChType: P; SizeZ_mm: 1.1; SizeY_mm: 3.0; Value1: 0.031 ohm; VdsMax_V: -20V; Value: -20V; Rdson45_ohm: 0.031; SizeArea_mm2: 7.5; QgTyp_nC: 12.5; ChMode: Enhancement; SizeAreaWB_mm2: 14.0
Q5 = CMP-0000419-2: Transistor, NPN, 40 V, 0.2 A, SOT-23; Manufacturer: ON Semiconductor; TaMax_C: 150°C; Value2: 300; Value1: 0.2 A; Vcesat1_V: 3dV; SizeX_mm: 2.5; SizeY_mm: 3; TaMin_C: -55°C; IcRated_A: 2dA; CompType: BJT; SizeZ_mm: 1.1; Value: 40 V; SizeArea_mm2: 7.5; NPN: 1; Vceo_V: 40V; PNP: 0; AEC Category: Q101; SizeAreaWB_mm2: 14; U/M: EA
R15 R28 = CMP-0022002-4: as R90 on sheet BOOST- SEPIC
R34 R49 = CMP-0022068-4: RES, 15.8 k, 1%, 0.1 W, AEC-Q200 Grade 0, 0603; Manufacturer: Vishay-Dale; Power_W: 100mW; TempCo: 100 ppm/C; Value_Code: 15k8; Value: 15.8k; EIA_Code: E96; SizeX_mm: 1.6; SizeY_mm: 0.8; SizeZ_mm: 1; Value2: 0.1W; SizeArea_mm2: 1.28; AEC Qualified: Y; VDC_V: 75V; AEC Category: Q200; AEC Grade: 0
R35 R52 = CMP-0015068-3: RES, 0.1, 1%, 0.33 W, AEC-Q200 Grade 1, 1210; Manufacturer: Panasonic; Alternate Manufacturer: Yageo; Alternate PartNumber: RL1210FR-070R1L; Power_W: 330mW; TempCo: 100 ppm/C; Value_Code: R100; Value: 0.1; EIA_Code: E96; Res_ohm: 1d; SizeX_mm: 3.2; SizeY_mm: 2.5; SizeZ_mm: 1.35; SizeArea_mm2: 8; CompType: Resistor; AEC Qualified: Y; AEC Grade: 1; AEC Category: Q200; SizeAreaWB_mm2: 14.7
R36 R43 R51 = CMP-0022109-5: RES, 1.00 k, 1%, 0.1 W, AEC-Q200 Grade 0, 0603; Manufacturer: Vishay-Dale; Power_W: 100mW; TempCo: 100 ppm/C; Value_Code: 1k00; Value: 1.00k; EIA_Code: E96; Res_ohm: 1k; SizeX_mm: 1.6; SizeY_mm: 0.8; SizeZ_mm: 1; Value2: 0.1W; SizeArea_mm2: 1.28; AEC Qualified: Y; VDC_V: 75V; AEC Category: Q200; AEC Grade: 0
R37 R53 = CMP-0022324-4: RES, 30.1 k, 1%, 0.1 W, AEC-Q200 Grade 0, 0603; Manufacturer: Vishay-Dale; Power_W: 100mW; TempCo: 100 ppm/C; Value_Code: 30k1; Value: 30.1k; EIA_Code: E96; SizeX_mm: 1.6; SizeY_mm: 0.8; SizeZ_mm: 1; Value2: 0.1W; SizeArea_mm2: 1.28; AEC Qualified: Y; VDC_V: 75V; AEC Category: Q200; AEC Grade: 0
R38 R40 = CMP-0022200-4: as R5 on sheet BOOST- SEPIC
R39 R41 = CMP-0021998-4: as R23 on sheet BOOST- SEPIC
R42 R45 = CMP-0025874-4: RES, 0, 5%, 0.1 W, AEC-Q200 Grade 0, 0603; Manufacturer: Panasonic; Power_W: 100mW; TempCo: 600 ppm/C; Value_Code: 0000; Value: 0; EIA_Code: E24; SizeX_mm: 1.6; SizeY_mm: 0.8; SizeZ_mm: 1; Value2: 0.1W; SizeArea_mm2: 1.28; CompType: Resistor; AEC Qualified: Y; VDC_V: 50V; AEC Category: Q200; SizeAreaWB_mm2: 4.68
R46 R48 R50 = CMP-0023341-3: as R7 on sheet BOOST- SEPIC
R47 = CMP-0022237-4: RES, 24.9 k, 1%, 0.1 W, AEC-Q200 Grade 0, 0603; Manufacturer: Vishay-Dale; Power_W: 100mW; TempCo: 100 ppm/C; Value_Code: 24k9; Value: 24.9k; EIA_Code: E96; SizeX_mm: 1.6; SizeY_mm: 0.8; SizeZ_mm: 1; Value2: 0.1W; SizeArea_mm2: 1.28; CompType: Resistor; AEC Qualified: Y; VDC_V: 75V; AEC Category: Q200; AEC Grade: 0
U2 = CMP-0085387-1: 4.5 to 65-V Input Dual 1.6-A Synchronous Buck LED Driver with SPI Control, DAP0032A (HTSSOP-32); Alternate PartNumber: TPS92520QDAPQ1; Manufacturer: Texas Instruments; SizeZ_mm: 1.2; SizeAreaWB_mm2: 131.3; AEC Qualified: Y; SizeArea_mm2: 89.1; AEC Category: Q200; SizeX_mm: 8.1; SizeY_mm: 11; CompType: IC

## Sheet EVM_Hardware.SchDoc
size 431 x 279 mm; Date: Not shown in title block; ApprovedBy: Not shown in title block; CheckedBy: Not shown in title block; Author: Not shown in title block; CompanyName: Not shown in title block; Engineer: Not shown in title block; Organization: Not shown in title block; Address1: Not shown in title block; Address2: Not shown in title block; Address3: Not shown in title block; Address4: Not shown in title block; DocumentNumber: 1; Revision: Use project parameter SCH_Rev; SheetNumber: 3; SheetTotal: 3; PageSetup: Record=PageOptions¦CenterHorizontal=True¦CenterVertical=True¦PrintScale=1.00¦XCorrection=1.00¦YCorrection=1.00¦PrintKind=0¦BorderSize=5000000¦LeftOffset=0¦BottomOffset=0¦Orientation=2¦PaperLength=1000¦PaperWidth=1000¦Scale=100¦PaperSource=15¦PrintQuality=600¦MediaType=1¦DitherType=10¦PaperKind=Letter¦PrintScaleMode=1
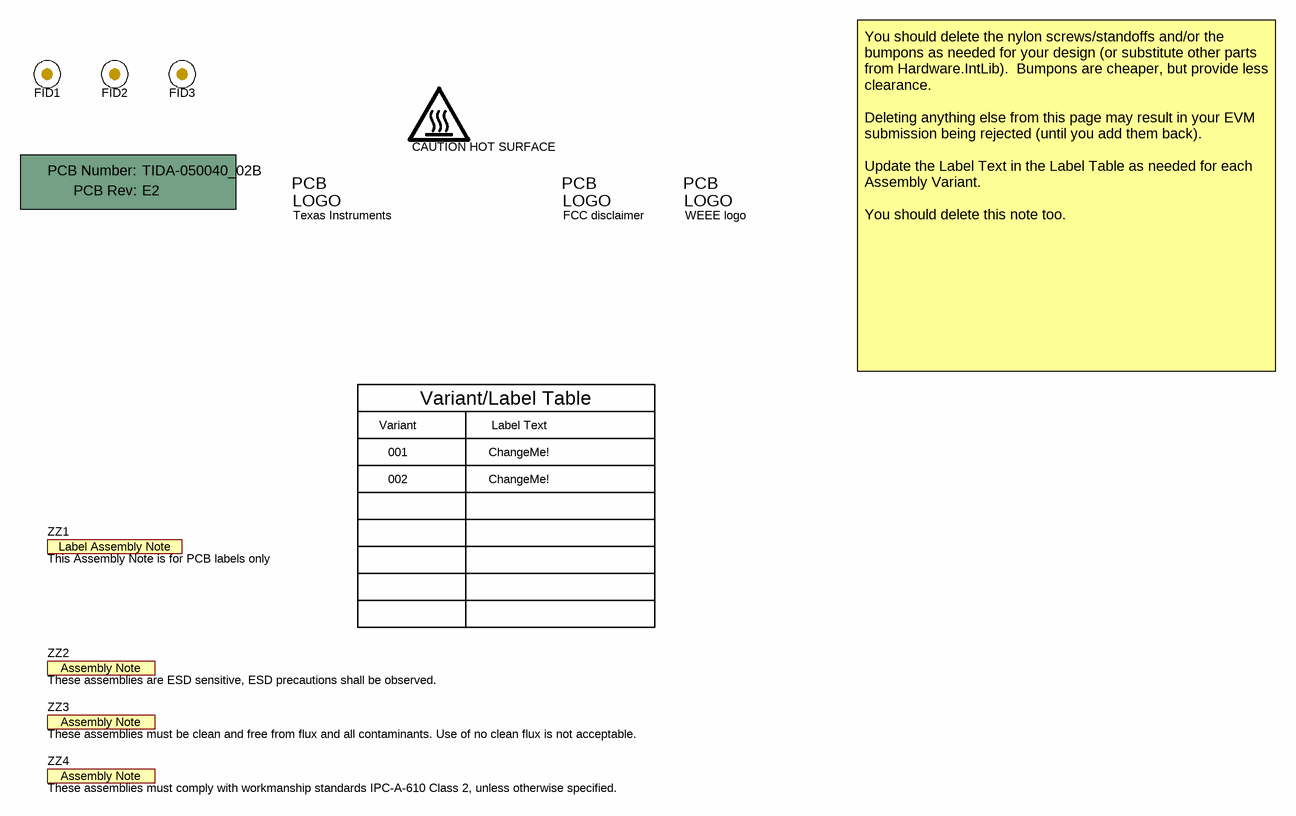
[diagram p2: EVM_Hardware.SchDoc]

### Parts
!PCB  Printed Circuit Board  (value not drawn)  (mechanical)
FID1  Fiducial  [Fiducial10-20]  (value not drawn)
FID2  Fiducial  [Fiducial10-20]  (value not drawn)
FID3  Fiducial  [Fiducial10-20]  (value not drawn)
Logo1  Texas Instruments  [TI_Stacked_Overlay_Small]  (no BOM)
LOGO2  CAUTION HOT SURFACE  [IEC_HotSurface_Small]  (no BOM)
Logo3  FCC disclaimer  [FCC_disclaimer]  (no BOM)
Logo4  WEEE logo  [WEEE_Minimum]  (no BOM)
ZZ1  This Assembly Note is for PCB labels only  [AssemblyNoteLabel]  (no BOM)
ZZ2  These assemblies are ESD sensitive, ESD precautions shall be observed.  [AssemblyNote]  (no BOM)
ZZ3  These assemblies must be clean and free from flux and all contaminants. Use of no clean flux is not acceptable.  [AssemblyNote]  (no BOM)
ZZ4  These assemblies must comply with workmanship standards IPC-A-610 Class 2, unless otherwise specified.  [AssemblyNote]  (no BOM)

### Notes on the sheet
- Variant
- Variant/Label Table
- Label Text
- You should delete the nylon screws/standoffs and/or the bumpons as needed for your design (or substitute other parts from Hardware.IntLib).  Bumpons are cheaper, but provide less clearance.
  Deleting anything else from this page may result in your EVM submission being rejected (until you add them back).
  Update the Label Text in the Label Table as needed for each Assembly Variant.
  You should delete this note too.
- 001
- 002
- ChangeMe!

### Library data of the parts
!PCB = CMP-0003618-2: Manufacturer: Any; PartNumber: TIDA-050040_02B
FID1-FID3 = CMP-0077181-1: Fiducial mark.  There is nothing to buy or mount.
Logo1 = CMP-0074838-1: Texas Instrument Corporate Signature; SymbolCreator: a0412235; Lib Reference: TI_Logo; Library Reference: Logo
LOGO2 = CMP-0074837-1: IEC 61010-1 Hot Surface Warning; SymbolCreator: a0412235; Lib Reference: IEC_HotSurface
Logo3 = CMP-0074847-1: FCC_disclaimer; Library Reference: Logo
Logo4 = CMP-0074769-1
ZZ1 = CMP-0003616-3
ZZ2 = CMP-0077236-1
ZZ3 = CMP-0077237-1
ZZ4 = CMP-0077238-1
